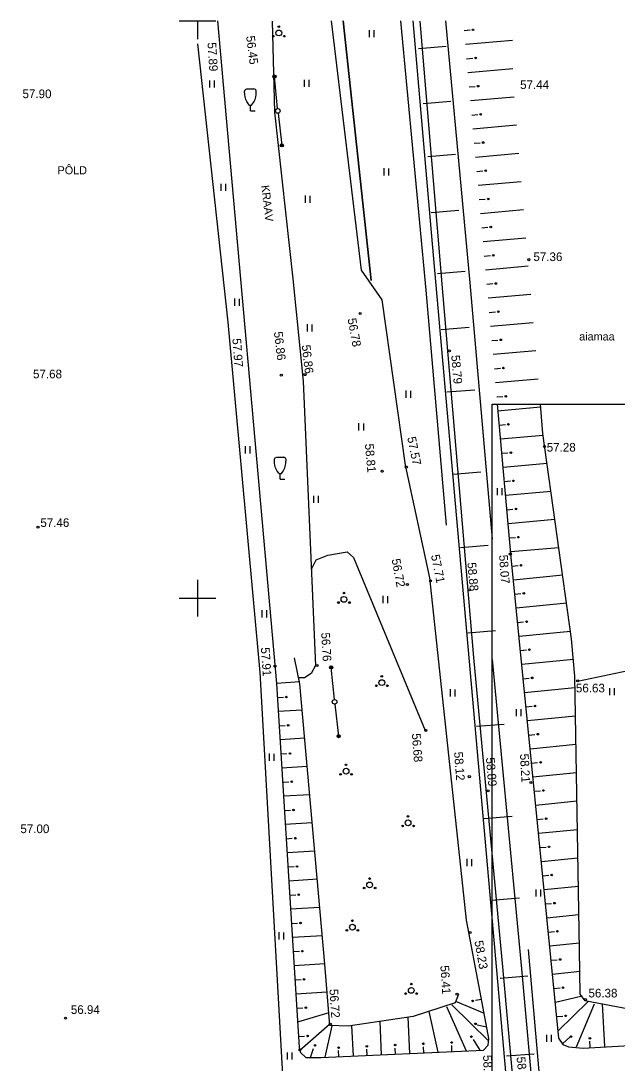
# Model space of a CAD drawing. Extents: x 9156 to 9809, y 2728 to 4000.
# Drawn here: x 9234.7 to 9286.3, y 3909.7 to 4000 of the extents above; entities that cross this region are included whole.
import ezdxf

# ---------------------------------------------------------------- set-up
doc = ezdxf.new("R2010")
doc.units = 0
doc.layers.add('Level 54', color=7, linetype='Continuous')
doc.layers.add('Level 63', color=7, linetype='Continuous')

msp = doc.modelspace()

# ---------------------------------------------------------------- linework, layer by layer
at = {"layer": 'Level 54'}
for p, q in [((9248.407, 4000), (9250, 4000)), ((9248.407, 4000), (9250, 4000)), ((9250, 4000), (9250, 3998.407)), ((9250, 4000), (9250, 3998.407)), ((9250, 4000), (9250, 3998.407)), ((9250, 4000), (9251.593, 4000)), ((9250, 4000), (9250, 3998.407)), ((9250, 4000), (9251.593, 4000)), ((9251.728, 4000), (9256.843, 3942.614)), ((9256.46, 3999.96), (9256.672, 3992.096)), ((9264.189, 3978.4), (9261.603, 4000)), ((9262.609, 4000), (9265.035, 3977.513)), ((9265.035, 3977.513), (9262.609, 4000)), ((9269.807, 3976.674), (9267.618, 4000)), ((9270.361, 3980.68), (9268.665, 4000)), ((9271.487, 4000), (9273.589, 3977.308)), ((9264.867, 3999.194), (9264.867, 3998.574)), ((9265.272, 3999.182), (9265.272, 3998.574)), ((9273.088, 3999.161), (9273.612, 3999.208)), ((9250.005, 3998.019), (9252.64, 3973.888)), ((9269.134, 3997.6), (9271.535, 3997.797)), ((9277.283, 3998.307), (9273.197, 3997.941)), ((9273.307, 3996.72), (9273.83, 3996.767)), ((9256.94, 3992.396), (9256.668, 3995.183)), ((9277.307, 3995.848), (9273.416, 3995.499)), ((9251.031, 3994.837), (9251.031, 3994.217)), ((9251.436, 3994.826), (9251.436, 3994.217)), ((9259.223, 3994.903), (9259.223, 3994.283)), ((9259.628, 3994.892), (9259.628, 3994.283)), ((9273.526, 3994.278), (9274.049, 3994.325)), ((9254.283, 3994.101), (9254.883, 3994.101)), ((9277.412, 3993.396), (9273.635, 3993.058)), ((9254.483, 3992.701), (9254.683, 3992.701)), ((9254.583, 3992.201), (9254.583, 3992.701)), ((9269.551, 3992.834), (9271.952, 3993.031)), ((9254.583, 3992.201), (9254.983, 3992.201)), ((9256.672, 3992.096), (9258.261, 3977.643)), ((9256.983, 3991.998), (9257.306, 3989.217)), ((9273.744, 3991.837), (9274.268, 3991.884)), ((9277.617, 3990.954), (9273.854, 3990.616)), ((9273.963, 3989.396), (9274.487, 3989.443)), ((9269.943, 3988.264), (9272.344, 3988.461)), ((9277.822, 3988.511), (9274.072, 3988.175)), ((9266.141, 3987.234), (9266.141, 3986.614)), ((9266.547, 3987.223), (9266.547, 3986.614)), ((9274.182, 3986.954), (9274.705, 3987.001)), ((9278.027, 3986.068), (9274.291, 3985.734)), ((9252.032, 3985.891), (9252.032, 3985.27)), ((9252.437, 3985.879), (9252.437, 3985.27)), ((9259.314, 3984.861), (9259.314, 3984.24)), ((9259.719, 3984.849), (9259.719, 3984.24)), ((9274.4, 3984.513), (9274.924, 3984.56)), ((9270.237, 3983.399), (9272.638, 3983.596)), ((9278.233, 3983.626), (9274.51, 3983.292)), ((9274.619, 3982.072), (9275.143, 3982.119)), ((9279.953, 3872.292), (9270.361, 3980.68)), ((9278.438, 3981.181), (9274.728, 3980.851)), ((9274.837, 3979.63), (9275.36, 3979.677)), ((9266.002, 3975.845), (9264.189, 3978.4)), ((9270.772, 3978.123), (9273.173, 3978.319)), ((9278.645, 3978.739), (9274.945, 3978.409)), ((9258.261, 3977.643), (9259.161, 3968.8)), ((9273.589, 3977.308), (9275.527, 3955.11)), ((9275.054, 3977.189), (9275.578, 3977.235)), ((9271.555, 3956.324), (9269.807, 3976.674)), ((9278.858, 3976.297), (9275.163, 3975.968)), ((9253.215, 3975.939), (9253.215, 3975.319)), ((9253.621, 3975.928), (9253.621, 3975.319)), ((9268.01, 3961.508), (9266.002, 3975.845)), ((9275.272, 3974.747), (9275.795, 3974.794)), ((9252.64, 3973.888), (9255.39, 3943.553)), ((9259.496, 3973.723), (9259.496, 3973.103)), ((9259.901, 3973.711), (9259.901, 3973.103)), ((9271.115, 3973.258), (9273.516, 3973.455)), ((9279.072, 3973.855), (9275.381, 3973.527)), ((9275.489, 3972.306), (9276.013, 3972.352)), ((9279.285, 3971.414), (9275.598, 3971.085)), ((9275.707, 3969.864), (9276.23, 3969.911)), ((9279.499, 3968.972), (9275.816, 3968.644)), ((9259.161, 3968.8), (9260.22, 3944.168)), ((9268.053, 3967.971), (9268.053, 3967.351)), ((9268.458, 3967.96), (9268.458, 3967.351)), ((9271.605, 3967.853), (9274.006, 3968.049)), ((9275.924, 3967.423), (9276.448, 3967.47)), ((9279.712, 3966.53), (9275.992, 3966.198)), ((9263.956, 3965.141), (9263.956, 3964.521)), ((9264.362, 3965.13), (9264.362, 3964.521)), ((9276.142, 3964.981), (9276.666, 3965.028)), ((9279.935, 3964.089), (9276.251, 3963.761)), ((9254.126, 3963.158), (9254.126, 3962.538)), ((9254.531, 3963.147), (9254.531, 3962.538)), ((9276.359, 3962.54), (9276.883, 3962.587)), ((9256.865, 3962.193), (9257.465, 3962.193)), ((9280.275, 3961.658), (9276.468, 3961.319)), ((9257.065, 3960.793), (9257.265, 3960.793)), ((9257.165, 3960.293), (9257.165, 3960.793)), ((9270.115, 3951.745), (9268.01, 3961.508)), ((9272.144, 3960.728), (9274.545, 3960.924)), ((9257.165, 3960.293), (9257.565, 3960.293)), ((9276.577, 3960.098), (9277.101, 3960.145)), ((9275.946, 3959.53), (9275.946, 3958.91)), ((9276.351, 3959.519), (9276.351, 3958.91)), ((9280.615, 3959.228), (9276.686, 3958.878)), ((9260.041, 3958.861), (9260.041, 3958.241)), ((9260.447, 3958.85), (9260.447, 3958.241)), ((9276.794, 3957.657), (9277.318, 3957.704)), ((9280.956, 3956.797), (9276.903, 3956.436)), ((9272.778, 3954.375), (9275.179, 3954.571)), ((9277.012, 3955.216), (9277.536, 3955.262)), ((9260.273, 3953.307), (9261.279, 3953.732)), ((9261.279, 3953.732), (9262.975, 3953.998)), ((9262.975, 3953.998), (9263.505, 3953.519)), ((9263.505, 3953.519), (9269.703, 3938.536)), ((9281.296, 3954.367), (9277.121, 3953.995)), ((9259.902, 3952.563), (9260.273, 3953.307)), ((9277.237, 3952.775), (9277.76, 3952.827)), ((9273.299, 3922.105), (9270.115, 3951.745)), ((9281.63, 3951.979), (9277.358, 3951.555)), ((9250, 3951.593), (9250, 3948.407)), ((9250, 3951.593), (9250, 3948.407)), ((9250, 3951.593), (9250, 3948.407)), ((9250, 3951.593), (9250, 3948.407)), ((9250, 3951.25), (9250, 3948.75)), ((9248.407, 3950), (9250, 3950)), ((9248.407, 3950), (9250, 3950)), ((9248.75, 3950), (9251.25, 3950)), ((9250, 3950), (9251.593, 3950)), ((9250, 3950), (9251.593, 3950)), ((9266.049, 3950.188), (9266.049, 3949.568)), ((9266.455, 3950.177), (9266.455, 3949.568)), ((9277.479, 3950.336), (9278.002, 3950.388)), ((9281.97, 3949.55), (9277.6, 3949.116)), ((9255.58, 3948.951), (9255.58, 3948.331)), ((9255.985, 3948.94), (9255.985, 3948.331)), ((9273.415, 3947.004), (9275.816, 3947.201)), ((9277.721, 3947.896), (9278.244, 3947.948)), ((9282.31, 3947.12), (9277.842, 3946.677)), ((9277.963, 3945.457), (9278.486, 3945.509)), ((9282.547, 3944.681), (9278.084, 3944.238)), ((9292.387, 3944.772), (9282.909, 3942.784)), ((9260.22, 3944.168), (9259.849, 3943.477)), ((9261.851, 3941.215), (9261.579, 3944.002)), ((9255.39, 3943.553), (9257.792, 3901.227)), ((9258.852, 3942.74), (9256.843, 3942.614)), ((9259.266, 3943.105), (9258.789, 3943.105)), ((9259.849, 3943.477), (9259.266, 3943.105)), ((9278.205, 3943.018), (9278.728, 3943.07)), ((9271.873, 3942.107), (9271.873, 3941.487)), ((9272.279, 3942.095), (9272.279, 3941.487)), ((9282.683, 3942.231), (9278.326, 3941.799)), ((9285.684, 3942.208), (9285.684, 3941.588)), ((9286.089, 3942.197), (9286.089, 3941.588)), ((9256.919, 3941.391), (9257.444, 3941.424)), ((9259.07, 3940.297), (9256.996, 3940.168)), ((9261.893, 3940.817), (9262.217, 3938.036)), ((9277.582, 3940.382), (9277.582, 3939.762)), ((9277.988, 3940.371), (9277.988, 3939.762)), ((9278.447, 3940.579), (9278.971, 3940.631)), ((9274.15, 3938.896), (9276.551, 3939.093)), ((9282.727, 3939.772), (9278.568, 3939.359)), ((9257.072, 3938.945), (9257.597, 3938.978)), ((9278.69, 3938.14), (9279.213, 3938.192)), ((9259.289, 3937.855), (9257.148, 3937.722)), ((9282.77, 3937.313), (9278.811, 3936.92)), ((9256.217, 3936.535), (9256.217, 3935.915)), ((9256.622, 3936.524), (9256.622, 3935.915)), ((9257.225, 3936.498), (9257.749, 3936.531)), ((9278.932, 3935.701), (9279.455, 3935.753)), ((9259.507, 3935.413), (9257.301, 3935.275)), ((9282.814, 3934.854), (9279.053, 3934.481)), ((9257.377, 3934.052), (9257.902, 3934.085)), ((9259.725, 3932.971), (9257.454, 3932.829)), ((9279.174, 3933.262), (9279.697, 3933.313)), ((9282.858, 3932.396), (9279.295, 3932.042)), ((9257.53, 3931.606), (9258.055, 3931.638)), ((9274.836, 3930.907), (9277.237, 3931.103)), ((9259.944, 3930.528), (9257.606, 3930.382)), ((9279.416, 3930.822), (9279.939, 3930.874)), ((9257.683, 3929.159), (9258.208, 3929.192)), ((9282.901, 3929.937), (9279.537, 3929.603)), ((9279.658, 3928.383), (9280.181, 3928.435)), ((9260.162, 3928.086), (9257.759, 3927.936)), ((9273.33, 3927.408), (9273.33, 3926.788)), ((9273.735, 3927.397), (9273.735, 3926.788)), ((9282.945, 3927.478), (9279.779, 3927.164)), ((9257.836, 3926.713), (9258.36, 3926.746)), ((9260.38, 3925.644), (9257.912, 3925.49)), ((9279.9, 3925.944), (9280.423, 3925.996)), ((9279.312, 3924.771), (9279.312, 3924.151)), ((9279.717, 3924.76), (9279.717, 3924.151)), ((9282.988, 3925.019), (9280.021, 3924.724)), ((9257.988, 3924.266), (9258.513, 3924.299)), ((9275.473, 3923.831), (9277.874, 3924.028)), ((9260.599, 3923.202), (9258.065, 3923.043)), ((9280.142, 3923.505), (9280.665, 3923.557)), ((9274.474, 3915.864), (9273.299, 3922.105)), ((9283.032, 3922.56), (9280.263, 3922.285)), ((9257.035, 3921.051), (9257.035, 3920.43)), ((9257.441, 3921.039), (9257.441, 3920.43)), ((9258.141, 3921.82), (9258.666, 3921.853)), ((9280.384, 3921.066), (9280.908, 3921.118)), ((9260.817, 3920.759), (9258.217, 3920.597)), ((9283.076, 3920.101), (9280.505, 3919.846)), ((9258.294, 3919.374), (9258.819, 3919.406)), ((9278.632, 3919.557), (9285.974, 3835.845)), ((9261.036, 3918.317), (9258.37, 3918.151)), ((9280.626, 3918.627), (9281.15, 3918.679)), ((9283.112, 3917.642), (9280.747, 3917.407)), ((9258.447, 3916.927), (9258.971, 3916.96)), ((9276.208, 3917.072), (9278.609, 3917.269)), ((9261.23, 3915.873), (9258.523, 3915.704)), ((9280.869, 3916.187), (9281.392, 3916.239)), ((9272.021, 3914.771), (9275.215, 3911.626)), ((9272.339, 3915.09), (9274.822, 3914.037)), ((9274.593, 3915.241), (9274.077, 3915.142)), ((9283.3, 3915.528), (9280.99, 3914.968)), ((9283.83, 3915.05), (9281.232, 3912.529)), ((9284.36, 3914.837), (9282.794, 3911.107)), ((9285.03, 3914.844), (9285.24, 3911.159)), ((9258.599, 3914.481), (9259.124, 3914.514)), ((9261.38, 3914.08), (9258.671, 3913.261)), ((9270.034, 3914.187), (9270.815, 3910.67)), ((9271.571, 3914.612), (9273.263, 3910.781)), ((9281.111, 3913.748), (9281.634, 3913.8)), ((9261.433, 3913.071), (9258.873, 3910.818)), ((9261.645, 3912.938), (9261.02, 3910.225)), ((9263.349, 3912.966), (9263.469, 3910.336)), ((9265.786, 3913.335), (9265.917, 3910.448)), ((9268.223, 3913.704), (9268.366, 3910.559)), ((9275.051, 3912.833), (9274.22, 3913.018)), ((9258.752, 3912.035), (9259.277, 3912.067)), ((9280.222, 3912.173), (9280.222, 3911.552)), ((9280.628, 3912.161), (9280.628, 3911.552)), ((9281.637, 3911.414), (9282.24, 3911.968)), ((9269.59, 3910.614), (9269.566, 3911.14)), ((9272.039, 3910.726), (9272.015, 3911.251)), ((9274.488, 3910.837), (9273.902, 3911.769)), ((9284.016, 3911.09), (9283.986, 3911.615)), ((9257.764, 3910.643), (9257.764, 3910.023)), ((9258.169, 3910.632), (9258.169, 3910.023)), ((9259.795, 3910.211), (9260.055, 3910.998)), ((9262.244, 3910.281), (9262.221, 3910.806)), ((9264.693, 3910.392), (9264.669, 3910.917)), ((9267.142, 3910.503), (9267.118, 3911.028)), ((9276.747, 3910.34), (9279.148, 3910.537))]:
    msp.add_line(p, q, dxfattribs=at)
for points in [[(9269.25, 3999.973), (9271.259, 3976.19), (9273.902, 3944.866), (9276.45, 3917.737), (9281.296, 3864.068), (9286.975, 3797.782), (9291.142, 3750)], [(9254.483, 3992.701), (9254.324, 3992.914), (9254.26, 3993.026), (9254.183, 3993.201), (9254.122, 3993.426), (9254.098, 3993.582), (9254.083, 3993.901), (9254.085, 3993.942), (9254.115, 3994.014), (9254.155, 3994.051), (9254.283, 3994.101)], [(9254.683, 3992.701), (9254.841, 3992.914), (9254.906, 3993.026), (9254.983, 3993.201), (9255.044, 3993.426), (9255.068, 3993.582), (9255.083, 3993.901), (9255.081, 3993.942), (9255.051, 3994.014), (9255.011, 3994.051), (9254.883, 3994.101)], [(9275.938, 3966.797), (9277.123, 3953.507), (9281.253, 3911.891), (9281.637, 3911.341), (9282.131, 3911.121), (9283.412, 3911.014), (9296.501, 3911.758)], [(9296.49, 3912.674), (9284.145, 3915.012), (9283.563, 3915.118), (9283.139, 3915.702), (9283.086, 3919.528), (9282.665, 3943.237), (9282.4, 3946.478), (9279.911, 3964.254), (9279.689, 3966.797)], [(9257.065, 3960.793), (9256.907, 3961.006), (9256.842, 3961.118), (9256.765, 3961.293), (9256.704, 3961.518), (9256.68, 3961.674), (9256.665, 3961.993), (9256.667, 3962.034), (9256.697, 3962.106), (9256.737, 3962.143), (9256.865, 3962.193)], [(9257.265, 3960.793), (9257.424, 3961.006), (9257.488, 3961.118), (9257.565, 3961.293), (9257.627, 3961.518), (9257.65, 3961.674), (9257.665, 3961.993), (9257.663, 3962.034), (9257.634, 3962.106), (9257.593, 3962.143), (9257.465, 3962.193)], [(9272.588, 3915.684), (9272.323, 3914.94), (9268.667, 3913.771), (9263.051, 3912.921), (9261.462, 3912.974), (9261.038, 3918.288), (9258.866, 3942.585), (9258.389, 3944.817)], [(9275.527, 3944.686), (9278.045, 3917.884), (9282.891, 3864.208), (9288.57, 3797.92), (9292.749, 3750)], [(9256.843, 3942.614), (9258.813, 3911.062), (9258.919, 3910.637), (9259.395, 3910.211), (9260.72, 3910.211), (9274.76, 3910.849), (9275.184, 3911.274), (9275.237, 3911.859), (9274.474, 3915.864)]]:
    msp.add_lwpolyline(points, dxfattribs=at)
for centre, radius in [((9257.044, 3999.499), 0.0707), ((9256.567, 3998.674), 0.0707), ((9257.044, 3998.949), 0.25), ((9257.52, 3998.674), 0.0707), ((9273.867, 3999.223), 0.0683), ((9274.086, 3996.782), 0.0683), ((9256.668, 3995.183), 0.136), ((9256.668, 3995.183), 0.121), ((9256.668, 3995.183), 0.107), ((9256.668, 3995.183), 0.0902), ((9256.668, 3995.183), 0.0749), ((9256.668, 3995.183), 0.0616), ((9256.668, 3995.183), 0.0468), ((9256.668, 3995.183), 0.0343), ((9256.668, 3995.183), 0.0209), ((9256.668, 3995.183), 0.0112), ((9274.304, 3994.341), 0.0683), ((9256.96, 3992.197), 0.2), ((9256.96, 3992.197), 0.2), ((9274.523, 3991.899), 0.0683), ((9257.306, 3989.217), 0.136), ((9257.306, 3989.217), 0.121), ((9257.306, 3989.217), 0.107), ((9257.306, 3989.217), 0.0902), ((9257.306, 3989.217), 0.0749), ((9257.306, 3989.217), 0.0616), ((9257.306, 3989.217), 0.0468), ((9257.306, 3989.217), 0.0343), ((9257.306, 3989.217), 0.0209), ((9257.306, 3989.217), 0.0112), ((9274.742, 3989.458), 0.0683), ((9274.961, 3987.017), 0.0683), ((9275.179, 3984.575), 0.0683), ((9275.398, 3982.134), 0.0683), ((9275.616, 3979.692), 0.0683), ((9278.695, 3979.31), 0.0909), ((9275.833, 3977.251), 0.0683), ((9264.085, 3974.654), 0.0909), ((9276.051, 3974.809), 0.0683), ((9276.268, 3972.368), 0.0683), ((9271.822, 3971.413), 0.0909), ((9276.486, 3969.926), 0.0683), ((9257.257, 3969.313), 0.0909), ((9259.306, 3969.359), 0.0909), ((9276.703, 3967.485), 0.0683), ((9276.921, 3965.043), 0.0683), ((9277.138, 3962.602), 0.0683), ((9280.053, 3963.129), 0.0909), ((9265.989, 3960.984), 0.0909), ((9268.082, 3961.349), 0.0909), ((9277.356, 3960.16), 0.0683), ((9277.573, 3957.719), 0.0683), ((9236.194, 3956.147), 0.0909), ((9277.791, 3955.277), 0.0683), ((9277.094, 3953.817), 0.0909), ((9278.015, 3952.844), 0.0683), ((9268.173, 3951.17), 0.0909), ((9270.176, 3951.489), 0.0909), ((9273.544, 3950.713), 0.0909), ((9262.684, 3949.889), 0.25), ((9262.684, 3950.439), 0.0707), ((9278.257, 3950.405), 0.0683), ((9262.207, 3949.614), 0.0707), ((9263.16, 3949.614), 0.0707), ((9278.499, 3947.966), 0.0683), ((9278.741, 3945.527), 0.0683), ((9256.706, 3944.11), 0.0909), ((9260.348, 3944.155), 0.0909), ((9261.579, 3944.002), 0.136), ((9261.579, 3944.002), 0.121), ((9261.579, 3944.002), 0.107), ((9261.579, 3944.002), 0.0902), ((9261.579, 3944.002), 0.0749), ((9261.579, 3944.002), 0.0616), ((9261.579, 3944.002), 0.0468), ((9261.579, 3944.002), 0.0343), ((9261.579, 3944.002), 0.0209), ((9261.579, 3944.002), 0.0112), ((9265.961, 3942.677), 0.25), ((9265.961, 3943.227), 0.0707), ((9278.983, 3943.088), 0.0683), ((9282.923, 3942.832), 0.0909), ((9265.484, 3942.402), 0.0707), ((9266.437, 3942.402), 0.0707), ((9257.699, 3941.432), 0.0683), ((9261.87, 3941.016), 0.2), ((9261.87, 3941.016), 0.2), ((9279.226, 3940.649), 0.0683), ((9257.852, 3938.986), 0.0683), ((9262.217, 3938.036), 0.136), ((9262.217, 3938.036), 0.121), ((9269.769, 3938.541), 0.0909), ((9279.468, 3938.21), 0.0683), ((9262.217, 3938.036), 0.107), ((9262.217, 3938.036), 0.0902), ((9262.217, 3938.036), 0.0749), ((9262.217, 3938.036), 0.0616), ((9262.217, 3938.036), 0.0468), ((9262.217, 3938.036), 0.0343), ((9262.217, 3938.036), 0.0209), ((9262.217, 3938.036), 0.0112), ((9258.005, 3936.54), 0.0683), ((9262.866, 3935.558), 0.0707), ((9279.71, 3935.77), 0.0683), ((9262.389, 3934.733), 0.0707), ((9262.866, 3935.008), 0.25), ((9263.342, 3934.733), 0.0707), ((9273.54, 3934.53), 0.0909), ((9258.158, 3934.093), 0.0683), ((9278.865, 3934.027), 0.0909), ((9275.178, 3933.297), 0.0909), ((9279.952, 3933.331), 0.0683), ((9258.31, 3931.647), 0.0683), ((9268.236, 3931.085), 0.0707), ((9280.194, 3930.892), 0.0683), ((9267.76, 3930.26), 0.0707), ((9268.236, 3930.535), 0.25), ((9268.713, 3930.26), 0.0707), ((9258.463, 3929.2), 0.0683), ((9280.436, 3928.453), 0.0683), ((9258.616, 3926.754), 0.0683), ((9264.908, 3925.707), 0.0707), ((9280.678, 3926.014), 0.0683), ((9264.431, 3924.882), 0.0707), ((9264.908, 3925.157), 0.25), ((9265.384, 3924.882), 0.0707), ((9258.769, 3924.308), 0.0683), ((9280.92, 3923.575), 0.0683), ((9258.921, 3921.861), 0.0683), ((9263.412, 3922.047), 0.0707), ((9262.936, 3921.222), 0.0707), ((9263.412, 3921.497), 0.25), ((9263.888, 3921.222), 0.0707), ((9273.606, 3921.032), 0.0909), ((9281.163, 3921.135), 0.0683), ((9259.074, 3919.415), 0.0683), ((9281.405, 3918.696), 0.0683), ((9259.227, 3916.969), 0.0683), ((9268.51, 3916.569), 0.0707), ((9268.033, 3915.744), 0.0707), ((9268.51, 3916.019), 0.25), ((9268.986, 3915.744), 0.0707), ((9272.468, 3915.691), 0.0909), ((9281.647, 3916.257), 0.0683), ((9273.824, 3915.102), 0.0683), ((9283.583, 3915.226), 0.0909), ((9259.379, 3914.522), 0.0683), ((9281.889, 3913.818), 0.0683), ((9238.577, 3913.615), 0.0909), ((9261.507, 3913.09), 0.0909), ((9274.07, 3913.119), 0.0683), ((9259.532, 3912.076), 0.0683), ((9273.718, 3912.016), 0.0683), ((9282.335, 3912.015), 0.0683), ((9260.173, 3911.258), 0.0683), ((9262.216, 3911.062), 0.0683), ((9264.665, 3911.173), 0.0683), ((9267.114, 3911.284), 0.0683), ((9269.562, 3911.395), 0.0683), ((9272.011, 3911.506), 0.0683), ((9283.979, 3911.87), 0.0683), ((9258.867, 3910.869), 0.0909)]:
    msp.add_circle(centre, radius, dxfattribs=at)
at = {"layer": 'Level 63'}
msp.add_lwpolyline([(9275.527, 3966.797), (9801.617, 3966.797), (9801.617, 3329.636), (9275.527, 3329.636)], close=True, dxfattribs=at)

# ---------------------------------------------------------------- texts
at = {"layer": 'Level 54'}
for s, height, rotation, p in [('56.45', 0.75, 277.25341, (9254.208, 3998.668)), ('57.89', 0.75, 273.56563, (9250.867, 3998.109)), ('KRAAV', 0.7, 276.69055, (9255.517, 3985.729)), ('56.78', 0.75, 280.40667, (9262.991, 3974.18)), ('56.86', 0.75, 276.89076, (9256.612, 3973.044)), ('57.97', 0.75, 274.0734, (9253.02, 3972.484)), ('56.86', 0.75, 276.54383, (9259.027, 3971.896)), ('58.79', 0.75, 275.08749, (9271.967, 3971.011)), ('57.57', 0.75, 281.27678, (9268.162, 3963.907)), ('58.81', 0.75, 275.10204, (9264.496, 3963.35)), ('57.71', 0.75, 281.27681, (9270.217, 3953.703)), ('58.07', 0.75, 274.01675, (9276.116, 3953.722)), ('56.72', 0.75, 280.39803, (9266.806, 3953.349)), ('58.88', 0.75, 275.12803, (9273.369, 3953.069)), ('56.76', 0.75, 273.26059, (9260.712, 3947.001)), ('57.91', 0.75, 273.93325, (9255.489, 3945.712)), ('56.68', 0.75, 274.25151, (9268.563, 3938.264)), ('58.12', 0.75, 274.38542, (9272.217, 3936.657)), ('58.21', 0.75, 273.29245, (9277.922, 3936.494)), ('58.89', 0.75, 274.82996, (9274.975, 3936.165)), ('58.23', 0.75, 279.97823, (9273.979, 3920.278)), ('56.41', 0.75, 273.84228, (9271.03, 3918.163)), ('56.72', 0.75, 273.80219, (9261.425, 3916.118)), ('58.29', 0.75, 272.11448, (9274.729, 3910.408)), ('58.89', 0.75, 276.05429, (9277.628, 3910.234))]:
    msp.add_text(s, height=height, rotation=rotation, dxfattribs=at).set_placement(p)
for s, height, p in [('57.44', 0.75, (9277.937, 3994.097)), ('57.90', 0.75, (9234.847, 3993.304)), ('PÔLD', 0.7, (9237.883, 3986.707)), ('57.36', 0.75, (9279.089, 3979.193)), ('aiamaa', 0.7, (9283.055, 3972.314)), ('57.68', 0.75, (9235.756, 3969.035)), ('57.28', 0.75, (9280.243, 3962.69)), ('57.46', 0.75, (9236.393, 3956.163)), ('56.63', 0.75, (9282.77, 3941.833)), ('57.00', 0.75, (9234.663, 3929.642)), ('56.38', 0.75, (9283.856, 3915.409)), ('56.94', 0.75, (9239.032, 3913.981))]:
    msp.add_text(s, height=height, dxfattribs=at).set_placement(p)

doc.saveas('drawing.dxf')
